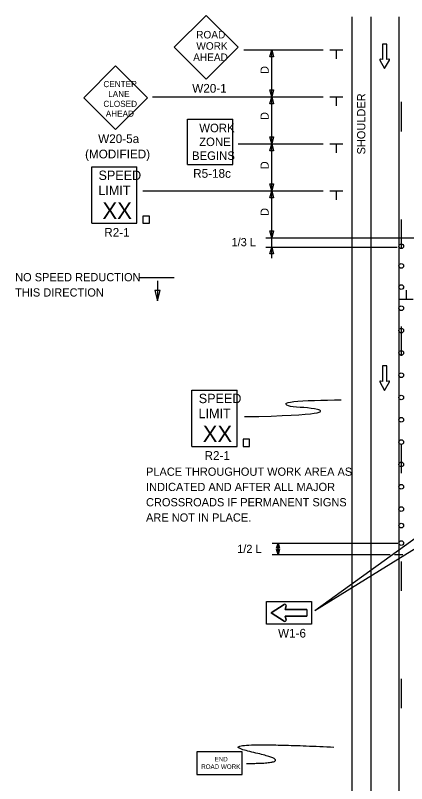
# Model space of a CAD drawing. Extents: x 16750 to 18296, y 5932 to 6919.
# Drawn here: x 16750 to 17082, y 6265 to 6919 of the extents above; entities that cross this region are included whole.
import ezdxf

# ---------------------------------------------------------------- set-up
doc = ezdxf.new("R2010")
doc.units = 0
for name, color, linetype in [('BORDER', 7, 'Continuous'), ('MT_SCRATCH_LEVEL_A', 7, 'Continuous'), ('MT_SCRATCH_LEVEL_E', 7, 'Continuous'), ('PAVT_EDGE_EX', 7, 'Continuous'), ('TRAFFIC_SIGNS_PR', 7, 'Continuous'), ('TYPICAL_EX', 7, 'Continuous'), ('TYPICAL_TEXT_DIMEN_EX', 7, 'Continuous'), ('TYPICAL_TEXT_DIMEN_PR', 7, 'Continuous')]:
    doc.layers.add(name, color=color, linetype=linetype)

msp = doc.modelspace()

# ---------------------------------------------------------------- linework, layer by layer
at = {"layer": 'BORDER'}
msp.add_line((17051.59, 6917.57), (17051.59, 6063.18), dxfattribs=at)
at = {"layer": 'MT_SCRATCH_LEVEL_A'}
msp.add_line((17075.59, 6917.57), (17075.59, 6063.18), dxfattribs=at)
for points in [[(17077.59, 6845.22), (17077.59, 6820.22)], [(17077.59, 6745.22), (17077.59, 6720.22)], [(17077.59, 6654.22), (17077.59, 6629.22)], [(17077.59, 6554.22), (17077.59, 6529.22)], [(17077.59, 6454.22), (17077.59, 6429.22)], [(17077.59, 6354.22), (17077.59, 6329.22)]]:
    msp.add_lwpolyline(points, dxfattribs=at)
at = {"layer": 'MT_SCRATCH_LEVEL_E'}
for p, q in [((17065.33, 6894.53), (17061.59, 6894.53)), ((17061.59, 6894.53), (17061.59, 6881.27)), ((17065.33, 6894.53), (17061.59, 6894.53)), ((17061.59, 6894.53), (17061.59, 6881.27)), ((17065.33, 6881.27), (17065.33, 6894.53)), ((17065.33, 6881.27), (17065.33, 6894.53)), ((17059.33, 6880.9), (17063.48, 6873.66)), ((17059.33, 6880.9), (17063.48, 6873.66)), ((17061.59, 6881.27), (17059.81, 6881.59)), ((17061.59, 6881.27), (17059.81, 6881.59)), ((17063.48, 6873.66), (17067.59, 6880.9)), ((17063.48, 6873.66), (17067.59, 6880.9)), ((17067.11, 6881.59), (17065.33, 6881.27)), ((17067.11, 6881.59), (17065.33, 6881.27)), ((17065.33, 6620.66), (17061.59, 6620.66)), ((17061.59, 6620.66), (17061.59, 6607.4)), ((17065.33, 6620.66), (17061.59, 6620.66)), ((17061.59, 6620.66), (17061.59, 6607.4)), ((17065.33, 6607.4), (17065.33, 6620.66)), ((17065.33, 6607.4), (17065.33, 6620.66)), ((17059.33, 6607.03), (17063.48, 6599.79)), ((17059.33, 6607.03), (17063.48, 6599.79)), ((17061.59, 6607.4), (17059.81, 6607.72)), ((17061.59, 6607.4), (17059.81, 6607.72)), ((17063.48, 6599.79), (17067.59, 6607.03)), ((17063.48, 6599.79), (17067.59, 6607.03)), ((17067.11, 6607.72), (17065.33, 6607.4)), ((17067.11, 6607.72), (17065.33, 6607.4))]:
    msp.add_line(p, q, dxfattribs=at)
for centre, start, end in [((17059.74, 6881.13), 80.03619, 209.77312), ((17059.74, 6881.13), 80.03619, 209.77312), ((17067.18, 6881.13), 330.42484, 99.96381), ((17067.18, 6881.13), 330.42484, 99.96381), ((17059.74, 6607.26), 80.03619, 209.77312), ((17059.74, 6607.26), 80.03619, 209.77312), ((17067.18, 6607.26), 330.42484, 99.96381), ((17067.18, 6607.26), 330.42484, 99.96381)]:
    msp.add_arc(centre, 0.463, start, end, dxfattribs=at)
at = {"layer": 'PAVT_EDGE_EX'}
msp.add_line((17035.59, 6917.57), (17035.59, 6063.18), dxfattribs=at)
at = {"layer": 'TRAFFIC_SIGNS_PR'}
for p, q in [((16911.72, 6918.94), (16884.53, 6891.76)), ((16938.9, 6891.76), (16911.72, 6918.94)), ((16884.53, 6891.76), (16911.72, 6864.57)), ((16911.72, 6864.57), (16938.9, 6891.76)), ((16834.77, 6876), (16807.62, 6848.85)), ((16861.92, 6848.85), (16834.77, 6876)), ((16807.62, 6848.85), (16834.77, 6821.7)), ((16834.77, 6821.7), (16861.92, 6848.85)), ((16895.87, 6792.15), (16895.87, 6830.55)), ((16895.87, 6830.55), (16934.27, 6830.55)), ((16934.27, 6792.15), (16934.27, 6830.55)), ((16814.42, 6789.98), (16852.82, 6789.98)), ((16814.42, 6741.98), (16814.42, 6789.98)), ((16852.82, 6741.98), (16852.82, 6789.98)), ((16895.87, 6792.15), (16934.27, 6792.15)), ((16814.42, 6741.98), (16852.82, 6741.98)), ((16899.66, 6600.05), (16938.06, 6600.05)), ((16899.66, 6552.05), (16899.66, 6600.05)), ((16938.06, 6552.05), (16938.06, 6600.05)), ((16899.66, 6552.05), (16938.06, 6552.05)), ((16978.04, 6417.53), (16966.88, 6410.42)), ((16978.88, 6413.22), (16979.72, 6416.28)), ((16966.88, 6410.42), (16978.04, 6403.32)), ((16997.28, 6413.22), (16978.88, 6413.22)), ((16997.28, 6413.22), (16997.28, 6407.62)), ((16979.72, 6404.56), (16978.88, 6407.62)), ((16978.88, 6407.62), (16997.28, 6407.62))]:
    msp.add_line(p, q, dxfattribs=at)
for points in [[(16857.84, 6741.98), (16863.43, 6741.98), (16863.43, 6748.15), (16857.84, 6748.15)], [(16943.08, 6552.05), (16948.67, 6552.05), (16948.67, 6558.22), (16943.08, 6558.22)], [(17001.28, 6400.82), (16962.88, 6400.82), (16962.88, 6420.02), (17001.28, 6420.02)], [(16903.9, 6272.91), (16942.3, 6272.91), (16942.3, 6292.11), (16903.9, 6292.11)]]:
    msp.add_lwpolyline(points, close=True, dxfattribs=at)
for points in [[(16978.04, 6403.32), (16966.88, 6410.42), (16978.04, 6417.53)], [(16979.72, 6416.28), (16978.88, 6413.22), (16997.28, 6413.22), (16997.28, 6407.62), (16978.88, 6407.62), (16979.72, 6404.56)]]:
    msp.add_lwpolyline(points, dxfattribs=at)
for centre in [(17077.59, 6722.39), (17077.59, 6705.72), (17077.59, 6687.72), (17077.59, 6669.72), (17077.59, 6650.72), (17077.59, 6631.72), (17077.59, 6612.72), (17077.59, 6593.72), (17077.59, 6574.72), (17077.59, 6555.72), (17077.59, 6536.72), (17077.59, 6517.72), (17077.59, 6498.72), (17077.59, 6484.67), (17077.63, 6469.83)]:
    msp.add_circle(centre, 2, dxfattribs=at)
for centre, start, end in [((16978.64, 6416.58), 344.67308, 122.46963), ((16978.64, 6416.58), 344.67308, 122.46962), ((16978.64, 6404.27), 237.53038, 15.32692), ((16978.64, 6404.27), 237.53038, 15.32692)]:
    msp.add_arc(centre, 1.12, start, end, dxfattribs=at)
msp.add_open_spline([(16945.89, 6282.29), (16993.13, 6282.29), (16908.11, 6301.64), (17020.4, 6296.15)], degree=2, dxfattribs=at)
at = {"layer": 'TYPICAL_EX'}
for p, q in [((17016.74, 6889.59), (17027.99, 6889.59)), ((17022.37, 6889.59), (17022.37, 6881.81)), ((17016.74, 6849.59), (17027.99, 6849.59)), ((17022.37, 6849.59), (17022.37, 6841.81)), ((17016.74, 6809.59), (17027.99, 6809.59)), ((17022.37, 6809.59), (17022.37, 6801.81)), ((17016.74, 6769.59), (17027.99, 6769.59)), ((17022.37, 6769.59), (17022.37, 6761.81)), ((17082.04, 6677.17), (17082.04, 6684.95)), ((17087.66, 6677.17), (17076.41, 6677.17))]:
    msp.add_line(p, q, dxfattribs=at)
at = {"layer": 'TYPICAL_TEXT_DIMEN_PR'}
for p, q in [((16943.76, 6889.59), (17011.24, 6889.59)), ((16965.92, 6883.73), (16967.49, 6889.59)), ((16967.49, 6889.59), (16969.06, 6883.73)), ((16967.49, 6849.59), (16967.49, 6889.59)), ((16967.49, 6883.73), (16965.92, 6883.73)), ((16969.06, 6883.73), (16967.49, 6883.73)), ((16967.49, 6849.59), (16965.92, 6855.45)), ((16965.92, 6855.45), (16967.49, 6855.45)), ((16967.49, 6855.45), (16969.06, 6855.45)), ((16969.06, 6855.45), (16967.49, 6849.59)), ((16866.01, 6849.59), (17011.24, 6849.59)), ((16965.92, 6843.73), (16967.49, 6849.59)), ((16967.49, 6809.59), (16967.49, 6849.59)), ((16967.49, 6849.59), (16969.06, 6843.73)), ((16967.49, 6843.73), (16965.92, 6843.73)), ((16969.06, 6843.73), (16967.49, 6843.73)), ((16967.49, 6809.59), (16965.92, 6815.45)), ((16965.92, 6815.45), (16967.49, 6815.45)), ((16967.49, 6815.45), (16969.06, 6815.45)), ((16969.06, 6815.45), (16967.49, 6809.59)), ((16938.9, 6809.59), (17011.24, 6809.59)), ((16965.92, 6803.73), (16967.49, 6809.59)), ((16967.49, 6809.59), (16969.06, 6803.73)), ((16967.49, 6769.59), (16967.49, 6809.59)), ((16967.49, 6803.73), (16965.92, 6803.73)), ((16969.06, 6803.73), (16967.49, 6803.73)), ((16967.49, 6769.59), (16965.92, 6775.45)), ((16965.92, 6775.45), (16967.49, 6775.45)), ((16967.49, 6737.47), (16967.49, 6777.47)), ((16967.49, 6775.45), (16969.06, 6775.45)), ((16969.06, 6775.45), (16967.49, 6769.59)), ((16857.91, 6769.59), (17011.24, 6769.59)), ((16965.92, 6763.73), (16967.49, 6769.59)), ((16967.49, 6769.59), (16969.06, 6763.73)), ((16967.49, 6763.73), (16965.92, 6763.73)), ((16969.06, 6763.73), (16967.49, 6763.73)), ((16967.49, 6729.59), (16965.92, 6735.45)), ((16965.92, 6735.45), (16967.49, 6735.45)), ((16967.49, 6712.24), (16967.49, 6737.47)), ((16967.49, 6735.45), (16969.06, 6735.45)), ((16969.06, 6735.45), (16967.49, 6729.59)), ((16962.49, 6729.72), (17094.41, 6729.72)), ((16962.49, 6721.72), (17074.24, 6721.72)), ((16965.92, 6715.85), (16967.49, 6721.71)), ((16967.49, 6721.71), (16969.06, 6715.85)), ((16967.49, 6715.85), (16965.92, 6715.85)), ((16969.06, 6715.85), (16967.49, 6715.85)), ((16884.47, 6695.5), (16855.03, 6695.5)), ((16870.29, 6693), (16870.29, 6675.88)), ((16870.29, 6684.67), (16867.94, 6684.67)), ((16867.94, 6684.67), (16870.29, 6675.88)), ((16870.29, 6675.88), (16872.65, 6684.67)), ((16872.65, 6684.67), (16870.29, 6684.67)), ((17003.97, 6412.5), (17100.41, 6482.06)), ((16967.83, 6469.83), (17074.58, 6469.83)), ((16971.65, 6465.43), (16972.83, 6469.83)), ((16972.83, 6469.83), (16974.01, 6465.43)), ((16972.83, 6460), (16972.83, 6469.83)), ((17003.97, 6412.5), (17096.28, 6469.48)), ((16972.83, 6465.43), (16971.65, 6465.43)), ((16972.83, 6460), (16971.65, 6464.39)), ((16971.65, 6464.39), (16972.83, 6464.39)), ((16974.01, 6465.43), (16972.83, 6465.43)), ((16972.83, 6464.39), (16974.01, 6464.39)), ((16974.01, 6464.39), (16972.83, 6460)), ((16967.83, 6460), (17068.15, 6460)), ((17071.78, 6460), (17079.06, 6460))]:
    msp.add_line(p, q, dxfattribs=at)
msp.add_open_spline([(16944.29, 6577.42), (17013.56, 6578.66), (17011.57, 6585.16), (16977.8, 6585.16), (16977.8, 6591.31), (17011.14, 6591.31), (17026.6, 6591.76)], degree=3, dxfattribs=at)

# ---------------------------------------------------------------- texts
at = {"layer": 'TRAFFIC_SIGNS_PR'}
for s, height, p in [('ROAD', 6.408, (16903.25, 6899.3)), ('WORK', 6.408, (16903.36, 6889.69)), ('AHEAD', 6.408, (16900.66, 6880.08)), ('CENTER', 5.2, (16824.35, 6857.85)), ('W20-1', 7.449, (16899.87, 6853.12)), ('LANE', 5.2, (16828.42, 6849.45)), ('CLOSED', 5.2, (16824.35, 6841.05)), ('AHEAD', 5.2, (16826.38, 6832.65)), ('WORK', 7.217, (16905.87, 6819.52)), ('W20-5a', 7.44, (16819.91, 6810.26)), ('ZONE', 7.217, (16905.75, 6807.71)), ('(MODIFIED)', 7.44, (16808.77, 6797.22)), ('BEGINS', 7.217, (16899.68, 6795.9)), ('R5-18c', 7.44, (16900.68, 6780.71)), ('SPEED', 8, (16820.19, 6778.84)), ('LIMIT', 8, (16820.03, 6766.04)), ('XX', 14.031, (16823.54, 6745.73)), ('R2-1', 7.44, (16825.1, 6730.53)), ('SPEED', 8, (16905.43, 6588.91)), ('LIMIT', 8, (16905.27, 6576.11)), ('XX', 14.031, (16908.78, 6555.81)), ('R2-1', 7.44, (16910.34, 6540.61)), ('PLACE THROUGHOUT WORK AREA AS', 7, (16860.59, 6527.09)), ('INDICATED AND AFTER ALL MAJOR', 7, (16860.59, 6514.09)), ('CROSSROADS IF PERMANENT SIGNS', 7, (16860.59, 6501.09)), ('ARE NOT IN PLACE.', 7, (16860.59, 6488.09)), ('W1-6', 7.44, (16972.82, 6389.38)), ('END', 3.831, (16918.9, 6284.05)), ('ROAD WORK', 3.831, (16907.51, 6277.66))]:
    msp.add_text(s, height=height, dxfattribs=at).set_placement(p)
at = {"layer": 'TYPICAL_TEXT_DIMEN_EX'}
msp.add_text('SHOULDER', height=7, rotation=90, dxfattribs=at).set_placement((17047.04, 6800.57))
at = {"layer": 'TYPICAL_TEXT_DIMEN_PR'}
for p in [(16964.93, 6869.05), (16964.93, 6829.87), (16964.93, 6787.96), (16964.93, 6748.21)]:
    msp.add_text('D', height=7, rotation=90, dxfattribs=at).set_placement(p)
for s, p in [('1/3 L', (16933.25, 6722.44)), ('NO SPEED REDUCTION', (16749.31, 6692.62)), ('THIS DIRECTION', (16749.31, 6679.62)), ('1/2 L', (16938.03, 6461.38))]:
    msp.add_text(s, height=7, dxfattribs=at).set_placement(p)

doc.saveas('drawing.dxf')
